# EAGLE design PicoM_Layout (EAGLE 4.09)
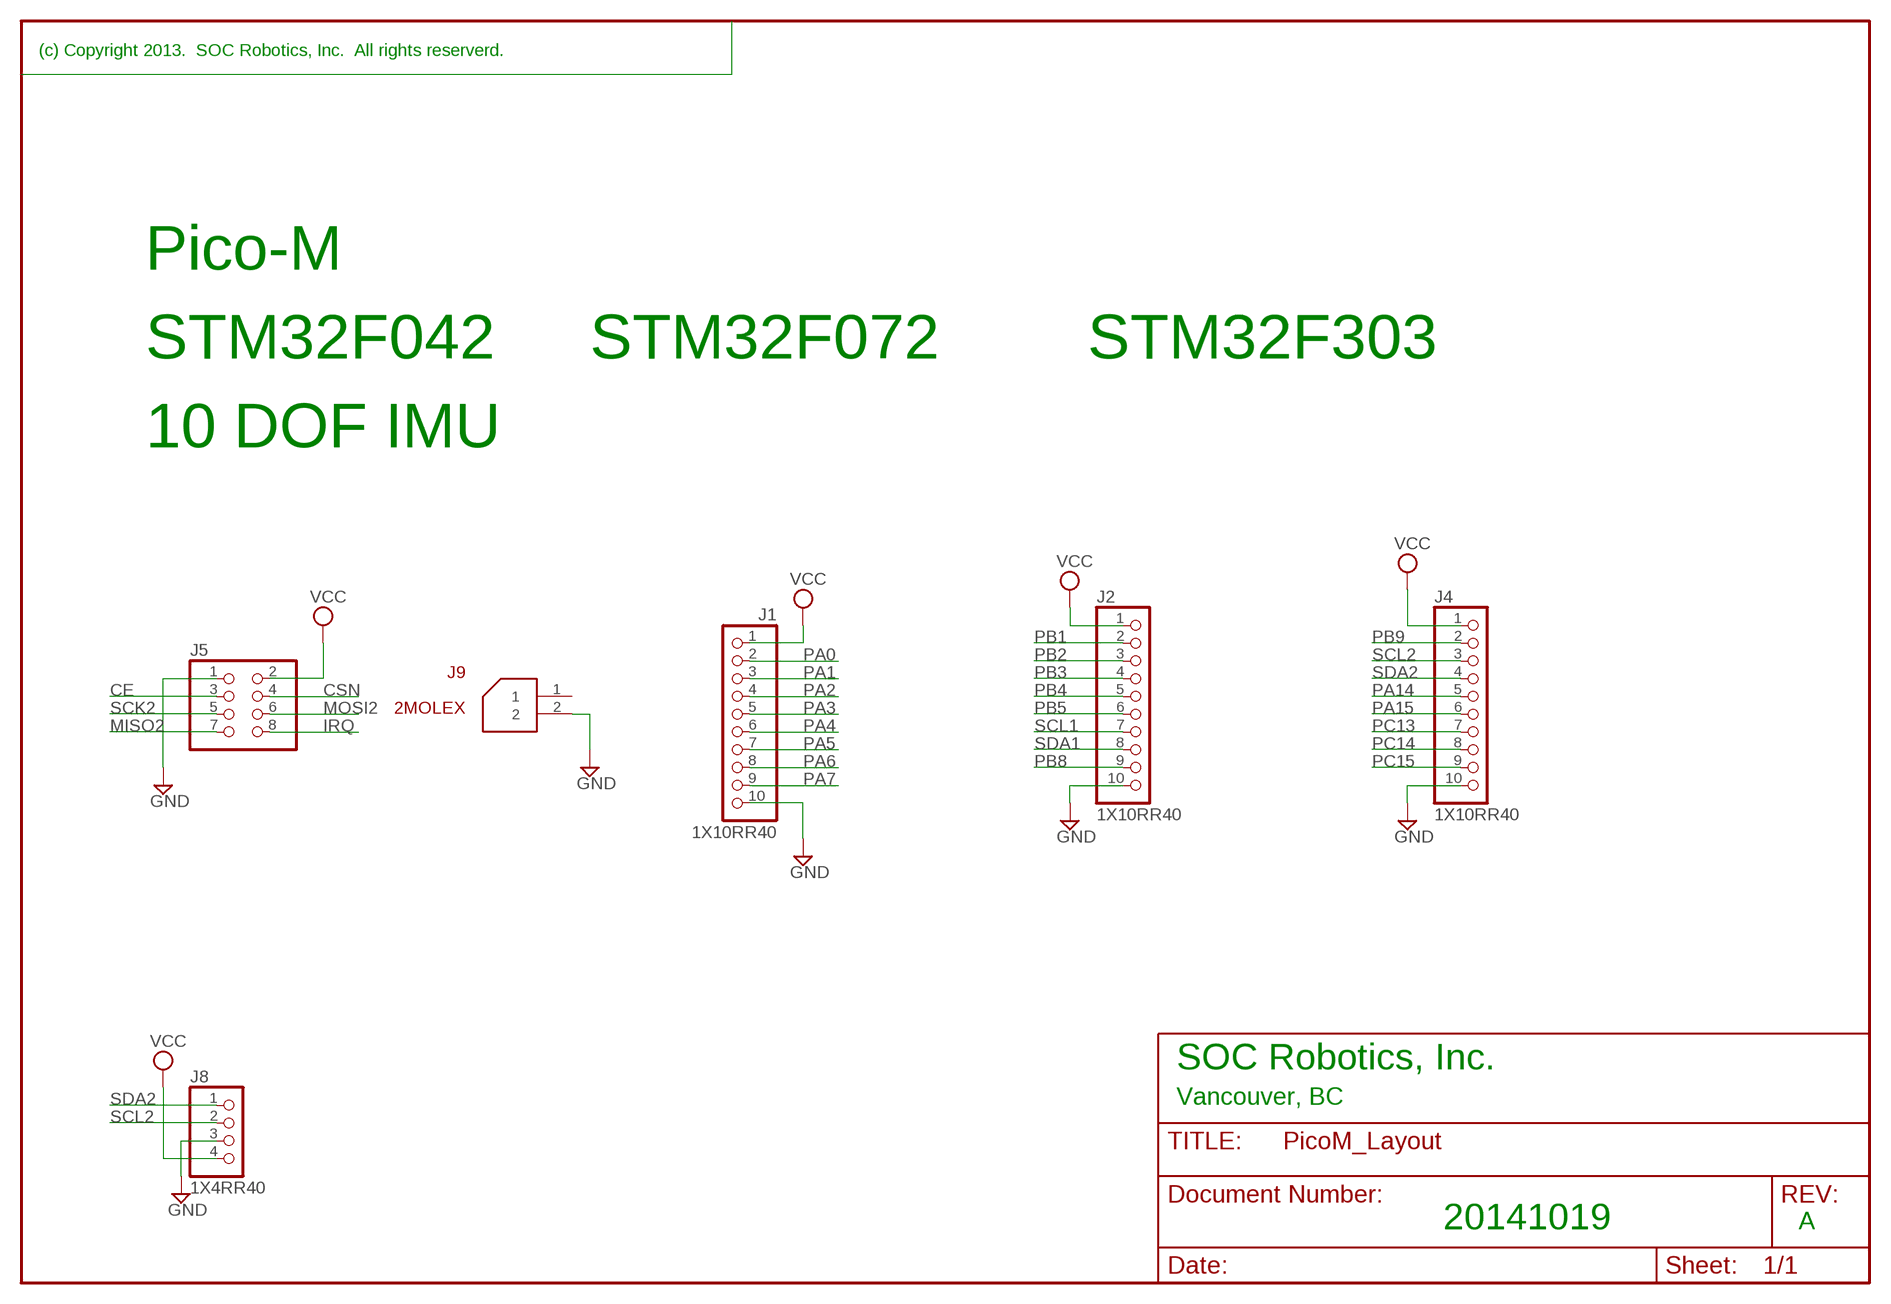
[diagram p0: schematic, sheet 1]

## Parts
J1  1X10RR40  PINH-1X10RR40  [1X10ROUND]
J2  1X10RR40  PINH-1X10RR40  [1X10ROUND]
J4  1X10RR40  PINH-1X10RR40  [1X10ROUND]
J5  PINHD-2X4HEX  [2X04]
J8  1X4RR40  PINH-1X4RR40  [1X4ROUND]
J9  2MOLEX  PINH-1X2MOLEX  [1X2MOLEX]

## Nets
CE: J5.3
CSN: J5.4
GND: J1.10 J2.10 J4.10 J5.1 J8.3 J9.2
IRQ: J5.8
MISO2: J5.7
MOSI2: J5.6
PA0: J1.2
PA1: J1.3
PA2: J1.4
PA3: J1.5
PA4: J1.6
PA5: J1.7
PA6: J1.8
PA7: J1.9
PA14: J4.5
PA15: J4.6
PB1: J2.2
PB2: J2.3
PB3: J2.4
PB4: J2.5
PB5: J2.6
PB8: J2.9
PB9: J4.2
PC13: J4.7
PC14: J4.8
PC15: J4.9
SCK2: J5.5
SCL1: J2.7
SCL2: J4.3 J8.2
SDA1: J2.8
SDA2: J4.4 J8.1
VCC: J1.1 J2.1 J4.1 J5.2 J8.4
Unconnected: J9.1

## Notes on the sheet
- (c) Copyright 2013.  SOC Robotics, Inc.  All rights reserverd.
- Pico-M
- STM32F042 | STM32F072 | STM32F303
- 10 DOF IMU
- SOC Robotics, Inc.
- Vancouver, BC
- 20141019 | A

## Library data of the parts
J1 J2 J4 = pinhead:PINH-1X10R
J5 = pinhead:PINHD-2X4: PIN HEADER
J8 = pinhead:PINH-1X4R: 1x4 Pin Head Round
J9 = pinhead:PINH-1X2MOLEX: 1x2 Molex 1.25mm thru-hole

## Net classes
1 VCC: width 0.305 mm, drill 0.203 mm, clearance 0.432 mm
2 GND: width 0.305 mm, drill 0.203 mm, clearance 0.432 mm
3 VTARGET: width 0.305 mm, drill 0.203 mm, clearance 0.432 mm
4 VIN: width 0.305 mm, drill 0.203 mm, clearance 0.432 mm

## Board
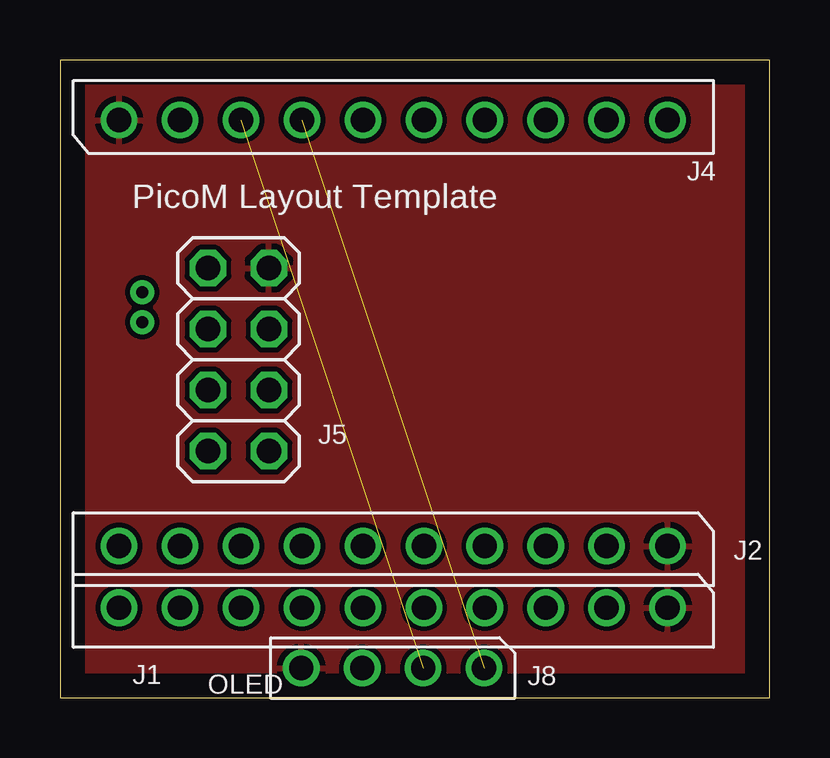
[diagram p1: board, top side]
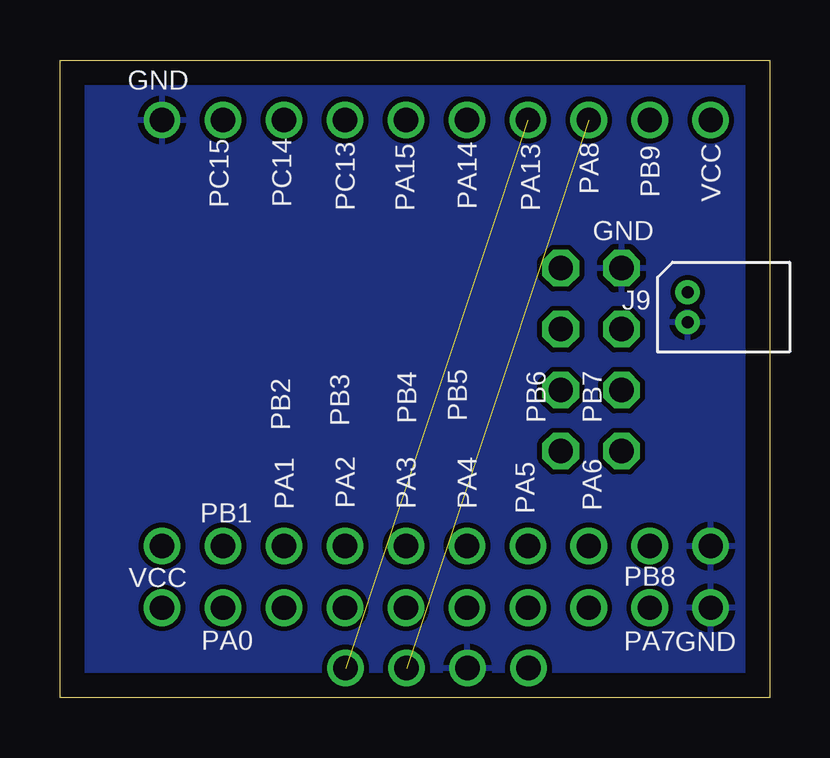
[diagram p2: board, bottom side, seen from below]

Size 29.57 x 26.57 mm. Coordinates in mm from the lower left corner, seen from the top.
Outline: 0,0 29.57,0 29.57,26.57 0,26.57 0,0
Copper layers used: Top, Bottom

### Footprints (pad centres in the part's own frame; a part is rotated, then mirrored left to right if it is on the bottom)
1X10ROUND = drill 1.016 round: 1 -11.43,0; 2 -8.89,0; 3 -6.35,0; 4 -3.81,0; 5 -1.27,0; 6 1.27,0; 7 3.81,0; 8 6.35,0; 9 8.89,0; 10 11.43,0
2X04 = drill 1.016 octagon: 1 -3.81,-1.27; 2 -3.81,1.27; 3 -1.27,-1.27; 4 -1.27,1.27; 5 1.27,-1.27; 6 1.27,1.27; 7 3.81,-1.27; 8 3.81,1.27
1X4ROUND = drill 1.016 round: 1 -3.81,0; 2 -1.27,0; 3 1.27,0; 4 3.81,0
1X2MOLEX = drill 0.5 pad 0.9 round: 1 0.625,0; 2 -0.625,0

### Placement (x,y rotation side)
J1  13.89,3.75 180 top
J2  13.89,6.31 180 top
J4  13.89,24.07 0 top
J5  7.44,14.08 270 top
J8  13.86,1.23 180 top
J9  3.42,16.27 90 bottom

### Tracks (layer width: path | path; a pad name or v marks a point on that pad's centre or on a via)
GND
  pour Bottom: 0.1,26.45 29.38,26.38 29.46,0.14 0.1,0.11
SCL2  (1 unrouted)
SDA2  (1 unrouted)
VCC
  pour Top: 0.1,26.45 29.43,26.45 29.46,0.11 0.1,0.11

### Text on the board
tPlace: PicoM Layout Template | OLED
bPlace: GND | VCC | PB9 | PA8 | PA13 | PA14 | PA15 | PC13 | PC14 | PC15 | GND | PB7 | PB6 | PB5 | PB4 | PB3 | PB2 | PA6 | PA5 | PA4 | PA3 | PA2 | PA1 | PB1 | PB8 | VCC | GND | PA0 | PA7
_tplace: R3 | C3 | J7 | C4 | J4 | C1 | L1 | R2 | C5 | U1 | C14 | LD1 | C9 | R9 | U2 | C2 | R6 | D1 | R4 | C7 | J5 | J1 | PicoM | U5 | R5 | C6 | R1 | J2 | R10 | J11 | J8 | OLED | J10
_bplace: GND | VCC | PB9 | PA8 | PA13 | PA14 | PA15 | PC13 | PC14 | PC15 | GND | R7 | BAT | R8 | C12 | C11 | C11 | J9 | PicoM | Q1 | SOC | C8 | PB7 | PB6 | PB5 | PB4 | U6 | 10DOF Sensor Node | PB3 | PB2 | L2 | PA6 | PA5 | PA4 | PA3 | PA2 | PA1 | PB1 | U4 | R11 | PB8 | VCC | GND | PA0 | PA7 | VCC | OLED | R12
